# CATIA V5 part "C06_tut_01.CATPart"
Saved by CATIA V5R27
Part number: Part1
Bounding box of the stored display mesh (mm): x -101.052 to 0, y -66 to 66, z 0 to 105.933
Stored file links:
  E:\_Deepak\2017_Deepak\CATIA\Resources\Tutorial Files\Tutorials\c06_catia_v5_6r2016_tut\C06_tut_01.CATPart
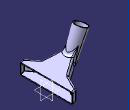
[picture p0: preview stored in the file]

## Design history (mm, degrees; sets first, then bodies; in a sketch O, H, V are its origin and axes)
Body1 (main body)
  Sketch1 on zx-plane, origin (0, 0, 0), H (-1, 0, 0), V (0, 0, 1)
    line L1 (0, 0) -> (0, 28)
    point P1 (0, 28)
    line L2 (0, 28) -> (61.837, 58.1599)
    line L3 (61.837, 58.1599) -> (61.837, 30.1599)
    line L4 (61.837, 30.1599) -> (0, 0)
    distance P1 H = 28
    angle L4 H = 26
    length L4 = 68.8
    vertical: L1 V, L3 V
    parallelism: L2 L4
  Pad1: profile Sketch1, direction (0, 1, 0), length 66, mirrored extent
  Sketch2 on face of Pad1 from Sketch1.L2, origin (11.0322, 0, 22.6193), H (0, 1, 0), V (-0.8988, 0, 0.4384)
    point P1 (-66, 12.2744)
    line L1 (-66, 12.2744) -> (-65.4759, 22.2744)
    line L2 (-65.4759, 22.2744) -> (-33, 37.2744)
    point P3 (-33, 37.2744)
    line L3 (-33, 37.2744) -> (-10.1992, 81.0744)
    line L4 (-10.1992, 81.0744) -> (10.1992, 81.0744)
    line L5 (10.1992, 81.0744) -> (33, 37.2744)
    point P6 (33, 37.2744)
    line L6 (33, 37.2744) -> (65.4759, 22.2744)
    point P7 (65.4759, 22.2744)
    line L7 (65.4759, 22.2744) -> (66, 12.2744)
    point P8 (66, 12.2744)
    line L8 (66, 12.2744) -> (-66, 12.2744)
    reference projected point E1 (66, 12.2744) from vertex [face of Pad1 from Sketch1.L1 | end face of Pad1 | face of Pad1 from Sketch1.L2]
    reference projected point E2 (-66, 12.2744) from vertex [face of Pad1 from Sketch1.L1 | start face of Pad1 | face of Pad1 from Sketch1.L2]
    reference projected line E3 (66, 81.0744) -> (66, 12.2744) from edge [face of Pad1 from Sketch1.L2 | end face of Pad1]
    reference projected line E4 (-66, 81.0744) -> (66, 81.0744) from edge [face of Pad1 from Sketch1.L2 | face of Pad1 from Sketch1.L3]
    angle L7 E3 = 3
    angle L3 L5 = 55
    distance P3 P6 = 66
    distance P7 L8 = 10
    distance P6 L8 = 25
    horizontal: L4 H, L8 H
    coincidence: P8 E1, P1 E2, L4 E4
    symmetry: L7 L1 V, L6 L2 V, L3 L5 V
  Pocket1: profile Sketch2, direction along edge [face of Pad1 from Sketch1.L1 | end face of Pad1], through (limit type 6), outer side
  Sketch3 on zx-plane, origin (0, 0, 0), H (-1, 0, 0), V (0, 0, 1)
    line L1 (61.837, 44.1599) -> (86.4446, 99.4294)
    point P1 (61.837, 44.1599)
    point P2 (86.4446, 99.4294)
    reference projected line E1 (22.4699, 10.9593) -> (61.837, 30.1599) from edge [face of Pad1 from Sketch1.L4 | face of Pocket1 from Sketch2.L5]
    reference projected line E2 (61.837, 58.1599) -> (61.837, 30.1599) from edge [face of Pocket1 from Sketch2.L5 | face of Pad1 from Sketch1.L3]
    reference projected point E3 (61.837, 58.1599) from vertex [face of Pocket1 from Sketch2.L5 | face of Pad1 from Sketch1.L2 | face of Pad1 from Sketch1.L3]
    angle L1 E1 = 140
    distance P1 E3 = 14
    length L1 = 60.5
    coincidence: P1 E2
  Plane1: type Normal, Curve Sketch3, RefPoint Sketch3.P2, Ratio 0
  Sketch4 on Plane1, origin (-51.2462, 0, 115.1008), H (0, -1, 0), V (0.9135, 0, 0.4067)
    circle A1 centre (0, -38.5295) radius 16
    point P1 (0, -38.5295)
    reference projected point E1 (0, -38.5295) from Sketch3.P2
    radius A1 = 16
    coincidence: P1 V, E1 P1
  Pad2: profile Sketch4, direction (-0.4067, 0, 0.9135), length 0, opposite side up to xy-plane
  Draft1: Angle -2, Neutral end face of Pad2, PullDir end face of Pad2, SupportToDraft face of Pad2 from Sketch4.A1
  Sketch5 on face of Pad1 from Sketch1.L4, origin (0, 0, 0), H (0, -1, 0), V (-0.8988, 0, 0.4384)
    line L1 (-57.0234, 118.908) -> (69.9188, 118.908)
    line L2 (69.9188, 118.908) -> (69.9188, 16.5882)
    line L3 (69.9188, 16.5882) -> (-57.0234, 16.5882)
    line L4 (-57.0234, 16.5882) -> (-57.0234, 118.908)
    horizontal: L1 H, L3 H
    vertical: L2 V, L4 V
  Pocket2: profile Sketch5, direction (-0.4384, 0, -0.8988), through (limit type 6)
  Fillet1: radius 12, on edge [face of Pad2 from Sketch4.A1 | face of Pad1 from Sketch1.L2]; edge [face of Pad2 from Sketch4.A1 | face of Pocket1 from Sketch2.L5]; edge [face of Pad2 from Sketch4.A1 | face of Pocket1 from Sketch2.L3]
  Fillet2: radius 3, on edge [face of Pad1 from Sketch1.L2 | face of Pocket1 from Sketch2.L5]; edge [face of Pad1 from Sketch1.L2 | face of Pocket1 from Sketch2.L3]; edge [face of Pocket1 from Sketch2.L2 | face of Pad1 from Sketch1.L2]; edge [face of Pocket1 from Sketch2.L1 | face of Pad1 from Sketch1.L2]; edge [face of Pocket1 from Sketch2.L7 | face of Pad1 from Sketch1.L2]; edge [face of Pocket1 from Sketch2.L6 | face of Pad1 from Sketch1.L2]; edge [face of Pocket1 from Sketch2.L6 | face of Pocket1 from Sketch2.L5]; edge [face of Pocket1 from Sketch2.L7 | face of Pocket1 from Sketch2.L6]; edge [face of Pocket1 from Sketch2.L6 | face of Pocket2]; edge [face of Pocket2 | face of Pocket1 from Sketch2.L7]; edge [face of Pocket1 from Sketch2.L5 | face of Pocket2]; edge [face of Pocket2 | face of Pocket1 from Sketch2.L2]; edge [face of Pocket1 from Sketch2.L1 | face of Pocket2]; edge [face of Pocket1 from Sketch2.L2 | face of Pocket1 from Sketch2.L1]; edge [face of Pocket1 from Sketch2.L3 | face of Pocket1 from Sketch2.L2]
  Shell1: ExtOffset 0, Face (end face of Pad2; face of Pad1 from Sketch1.L1), IntOffset 2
